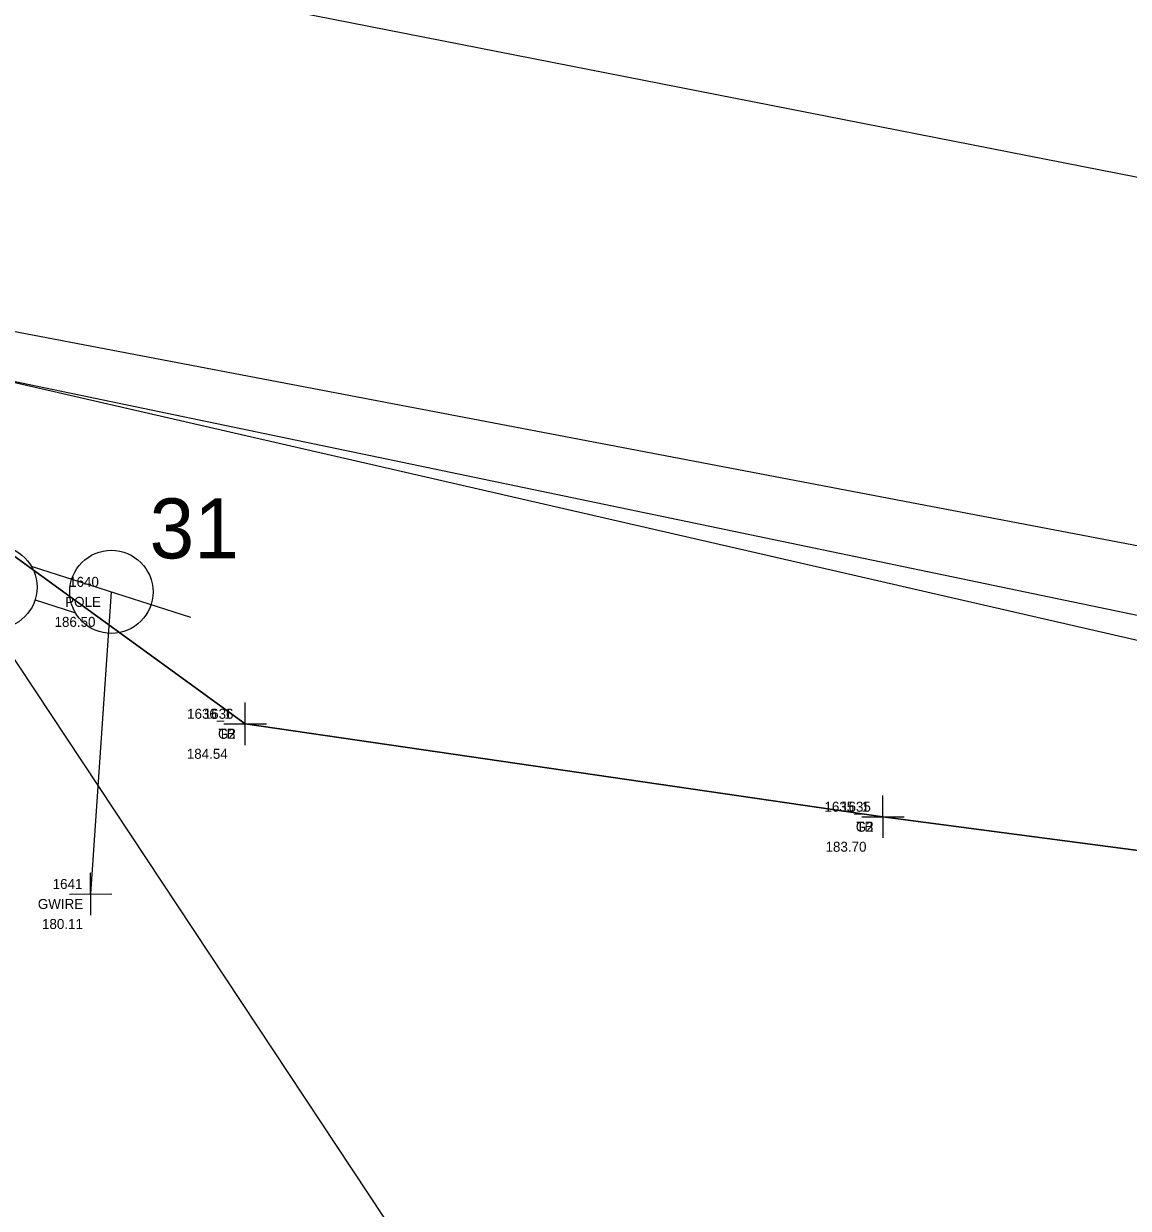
# Model space of a CAD drawing. Extents: x 1157913 to 1159198, y 600595 to 601244.
# Drawn here: x 1158733.31 to 1158766.44, y 600850.5 to 600886.03 of the extents above; entities that cross this region are included whole.
import ezdxf

# ---------------------------------------------------------------- set-up
doc = ezdxf.new("R2010")
doc.units = 0
for name, color, linetype in [('Default', 7, 'Continuous'), ('S_Fencing_Page', 7, 'Continuous'), ('S_Field_Code', 7, 'Continuous'), ('S_Ground_Elevation', 7, 'Continuous'), ('S_Guardrail_Beam', 7, 'Continuous'), ('S_Point_Elevation', 7, 'Continuous'), ('S_Point_Name', 7, 'Continuous'), ('S_Roadway_Centerline', 7, 'Continuous'), ('S_Roadway_Edge_Pavement', 7, 'Continuous'), ('S_Survey_Shot', 7, 'Continuous'), ('S_Text', 7, 'Continuous'), ('S_Trees_Bush_Line', 7, 'Continuous'), ('S_Utilities_GuyWire3', 7, 'Continuous'), ('S_Utilities_Pole_Power', 7, 'Continuous'), ('S_Utilities_Pole_Stub', 7, 'Continuous')]:
    doc.layers.add(name, color=color, linetype=linetype)

msp = doc.modelspace()

# ---------------------------------------------------------------- linework, layer by layer
at = {"layer": 'Default'}
msp.add_line((1158735.944, 600868.991), (1158735.944, 600868.991), dxfattribs=at)
at = {"layer": 'S_Fencing_Page'}
msp.add_lwpolyline([(1158746.867, 600785.067), (1158756.976, 600830.827), (1158729.37, 600872.505)], dxfattribs=at)
at = {"layer": 'S_Ground_Elevation'}
for points in [[(1158731.082, 600875.713), (1158772.256, 600867.139), (1158816.529, 600857.489), (1158865.273, 600847.952), (1158917.825, 600837.621), (1158968.021, 600827.258), (1159020.767, 600816.593), (1159040.966, 600812.564), (1159053.685, 600809.378), (1159069.908, 600805.655), (1159114.909, 600796.151), (1159123.756, 600788.147), (1159133.532, 600778.29), (1159138.615, 600758.547), (1159138.147, 600753.428)], [(1158785.697, 600858.736), (1158759.085, 600862.247), (1158739.956, 600865.034), (1158732.057, 600870.764), (1158730.106, 600872.462)]]:
    msp.add_lwpolyline(points, dxfattribs=at)
at = {"layer": 'S_Guardrail_Beam'}
msp.add_lwpolyline([(1159071.787, 600803.164), (1159053.685, 600809.378), (1159040.966, 600812.564), (1159020.767, 600816.593), (1158968.021, 600827.258), (1158917.825, 600837.621), (1158865.273, 600847.952), (1158816.529, 600857.489), (1158771.93, 600866.331), (1158731.082, 600875.713), (1158718.452, 600878.194)], dxfattribs=at)
at = {"layer": 'S_Roadway_Centerline'}
msp.add_lwpolyline([(1158721.055, 600890.395), (1158723.064, 600890.013), (1158776.46, 600879.509), (1158819.528, 600871.149), (1158868.15, 600861.085), (1158918.713, 600851.111), (1158970.46, 600840.7), (1159022.781, 600830.456), (1159075.358, 600819.935), (1159137.497, 600807.122), (1159188.145, 600796.962)], dxfattribs=at)
at = {"layer": 'S_Roadway_Edge_Pavement'}
msp.add_lwpolyline([(1158718.555, 600878.077), (1158720.622, 600877.678), (1158728.15, 600876.39), (1158731.242, 600877.14), (1158774.52, 600868.897), (1158817.183, 600860.346), (1158865.416, 600850.547), (1158917.771, 600840.45), (1158968.301, 600830.315), (1159021.332, 600819.61), (1159072.274, 600809.814), (1159120.871, 600799.427), (1159187.127, 600786.275)], dxfattribs=at)
at = {"layer": 'S_Survey_Shot'}
for p, q in [((1158739.957, 600864.398), (1158739.954, 600865.67)), ((1158739.957, 600864.398), (1158739.954, 600865.67)), ((1158739.32, 600865.033), (1158740.592, 600865.036)), ((1158739.32, 600865.033), (1158740.592, 600865.036)), ((1158739.956, 600865.034), (1158739.956, 600865.034)), ((1158739.956, 600865.034), (1158739.956, 600865.034)), ((1158759.087, 600861.61), (1158759.084, 600862.883)), ((1158759.087, 600861.61), (1158759.084, 600862.883)), ((1158758.449, 600862.245), (1158759.721, 600862.248)), ((1158758.449, 600862.245), (1158759.721, 600862.248)), ((1158759.085, 600862.247), (1158759.085, 600862.247)), ((1158759.085, 600862.247), (1158759.085, 600862.247)), ((1158735.324, 600859.294), (1158735.322, 600860.567)), ((1158734.687, 600859.929), (1158735.959, 600859.932)), ((1158735.323, 600859.93), (1158735.323, 600859.93))]:
    msp.add_line(p, q, dxfattribs=at)
at = {"layer": 'S_Trees_Bush_Line'}
msp.add_lwpolyline([(1158742.095, 600799.222), (1158718.764, 600834.195), (1158730.106, 600872.462), (1158732.057, 600870.764), (1158739.956, 600865.034), (1158759.085, 600862.247), (1158785.697, 600858.736), (1158818.083, 600854.565)], dxfattribs=at)
at = {"layer": 'S_Utilities_GuyWire3'}
msp.add_line((1158735.323, 600859.93), (1158735.323, 600859.93), dxfattribs=at)
msp.add_lwpolyline([(1158735.323, 600859.93), (1158735.944, 600868.991)], dxfattribs=at)
at = {"layer": 'S_Utilities_Pole_Power'}
msp.add_line((1158733.568, 600869.752), (1158738.32, 600868.23), dxfattribs=at)
msp.add_circle((1158735.944, 600868.991), 1.248, dxfattribs=at)
at = {"layer": 'S_Utilities_Pole_Stub'}
msp.add_line((1158733.654, 600868.75), (1158734.842, 600868.37), dxfattribs=at)
msp.add_circle((1158732.466, 600869.131), 1.248, dxfattribs=at)

# ---------------------------------------------------------------- texts
at = {"layer": 'S_Field_Code'}
for s, p in [('POLE', (1158734.558, 600868.541)), ('G2', (1158739.141, 600864.584)), ('TB', (1158739.155, 600864.584)), ('G2', (1158758.27, 600861.797)), ('TB', (1158758.284, 600861.797)), ('GWIRE', (1158733.738, 600859.48))]:
    msp.add_text(s, height=0.3, dxfattribs=at).set_placement(p)
at = {"layer": 'S_Point_Elevation'}
for s, p in [('186.50', (1158734.239, 600867.941)), ('184.54', (1158738.206, 600863.984)), ('184.54', (1158738.206, 600863.984)), ('183.70', (1158757.363, 600861.197)), ('183.70', (1158757.363, 600861.197)), ('180.11', (1158733.863, 600858.88))]:
    msp.add_text(s, height=0.3, dxfattribs=at).set_placement(p)
at = {"layer": 'S_Point_Name'}
for s, p in [('1640', (1158734.676, 600869.141)), ('1636_1', (1158738.215, 600865.184)), ('1636', (1158738.713, 600865.184)), ('1635_1', (1158757.33, 600862.397)), ('1635', (1158757.829, 600862.397)), ('1641', (1158734.182, 600860.08))]:
    msp.add_text(s, height=0.3, dxfattribs=at).set_placement(p)
at = {"layer": 'S_Text'}
msp.add_text('31', height=1.8, dxfattribs=at).set_placement((1158737.089, 600869.994))

doc.saveas('drawing.dxf')
